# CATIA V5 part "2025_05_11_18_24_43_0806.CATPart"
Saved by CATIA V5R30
Part number: 2025_05_11_18_24_43_0806
Definition: 2025_05_11_18_24_43_0806
Nomenclature: 2025_05_11_18_24_43_0806
Source: Unknown
Description: PART--DESC
Bounding box of the stored display mesh (mm): x -12.75 to 12.75, y -12.75 to 12.75, z 0 to 53
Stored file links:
  E:\Bakalarka\Model\Forma_v7\2025_05_11_18_24_43_0806.CATPart
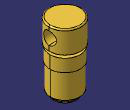
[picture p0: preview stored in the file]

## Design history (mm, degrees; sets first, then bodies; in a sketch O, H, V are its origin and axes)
Body1 "MANIFOLD_SOLID_BREP #164" (main body)
  Solid1: solid without history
